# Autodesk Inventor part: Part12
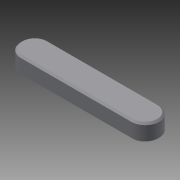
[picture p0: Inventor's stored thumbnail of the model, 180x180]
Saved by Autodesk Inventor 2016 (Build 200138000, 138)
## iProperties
Created: 2015-03
Part Number: Part12
Material: Generic
Document SubType Name: Modeling
Designer: Uglješa
Density: 1 g/cm^3
Appearance: Default
Author: Uglješa
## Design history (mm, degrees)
sketch "Sketch1"
  geometry: L1 (6.5, 0)-(18.5, 0) reference; L2 (6.5, -8)-(18.5, -8) reference; A1 r 4 centre (6.5, -4) between (6.5, 0) and (6.5, -8) reference; A2 r 4 centre (18.5, -4) between (18.5, -8) and (18.5, 0) reference; 1 further point
extrude "Extrusion1" new body sketch "Sketch1" distance "d3" = 5; taper "d4" = 0 deg
chamfer "Chamfer1" distance "d5" = 0.5; stored, may be unused: second distance "d6" = 2, angle "d7" = 45 deg
body "Solid1"
node "Reference1"
